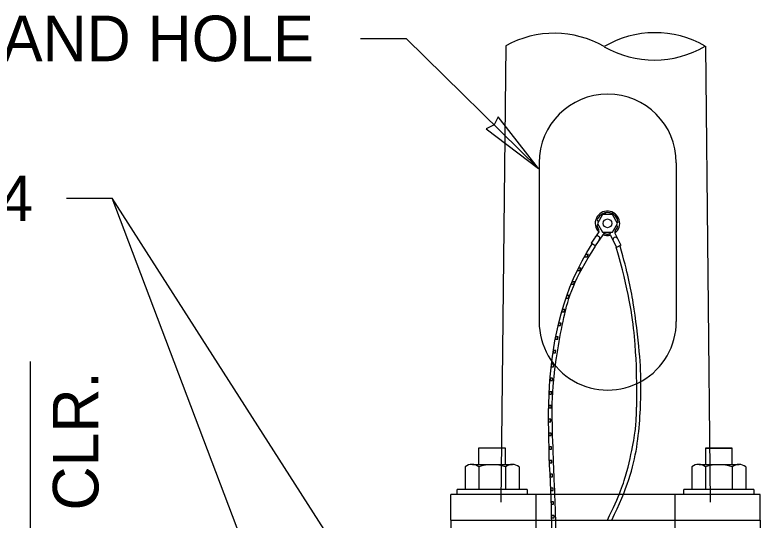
# Model space of a CAD drawing. Extents: x 99862 to 103680, y 99470 to 105076.
# Drawn here: x 101207 to 101468.4, y 103794.6 to 103971.8 of the extents above; entities that cross this region are included whole.
import ezdxf

# ---------------------------------------------------------------- set-up
doc = ezdxf.new("R2010")
doc.units = 0
for name, color, linetype in [('Level 12', 7, 'Continuous'), ('Level 13', 7, 'Continuous'), ('Level 15', 7, 'Continuous'), ('Level 16', 7, 'Continuous'), ('Level 20', 7, 'Continuous'), ('Level 3', 7, 'Continuous'), ('Level 32', 7, 'Continuous'), ('Level 4', 7, 'Continuous'), ('Level 7', 7, 'Continuous'), ('Level 8', 7, 'Continuous')]:
    doc.layers.add(name, color=color, linetype=linetype)

msp = doc.modelspace()

# ---------------------------------------------------------------- linework, layer by layer
at = {"layer": 'Level 12'}
for p, q in [((101390.88, 103919.95), (101390.88, 103864.27)), ((101438.99, 103919.95), (101438.99, 103864.27)), ((101364.96, 103813.37), (101364.96, 103805.45)), ((101367.48, 103814.17), (101381.51, 103814.17)), ((101369.69, 103813.37), (101369.69, 103805.45)), ((101379.14, 103813.29), (101379.14, 103805.37)), ((101383.87, 103813.29), (101383.87, 103805.37)), ((101444.45, 103813.37), (101444.45, 103805.45)), ((101446.97, 103814.17), (101461, 103814.17)), ((101449.18, 103813.37), (101449.18, 103805.45)), ((101458.64, 103813.29), (101458.64, 103805.37)), ((101463.36, 103813.29), (101463.36, 103805.37)), ((101386.72, 103805.41), (101362.11, 103805.41)), ((101362.11, 103803.65), (101362.11, 103805.41)), ((101386.72, 103805.41), (101386.72, 103803.65)), ((101466.21, 103805.41), (101441.6, 103805.41)), ((101441.6, 103803.65), (101441.6, 103805.41)), ((101466.21, 103805.41), (101466.21, 103803.65))]:
    msp.add_line(p, q, dxfattribs=at)
for centre, radius, start, end in [((101414.94, 103919.95), 24.06, 360, 180), ((101414.94, 103864.27), 24.06, 180, 0.0006), ((101367.32, 103810.27), 3.9, 52.6587, 127.3413), ((101374.27, 103798.55), 15.52, 71.7014, 107.1831), ((101381.51, 103810.56), 3.61, 49.0477, 130.9422), ((101446.82, 103810.27), 3.9, 52.6587, 127.3413), ((101453.76, 103798.55), 15.52, 71.7014, 107.1831), ((101461, 103810.56), 3.61, 49.0477, 130.9422)]:
    msp.add_arc(centre, radius, start, end, dxfattribs=at)
at = {"layer": 'Level 13'}
for p, q in [((101359.88, 103794.65), (101359.88, 103803.65)), ((101468.38, 103803.65), (101359.88, 103803.65)), ((101389.71, 103803.65), (101389.71, 103794.65)), ((101438.56, 103794.65), (101438.56, 103803.65)), ((101468.38, 103794.65), (101468.38, 103803.65))]:
    msp.add_line(p, q, dxfattribs=at)
at = {"layer": 'Level 15'}
for p, q in [((101328.28, 103963.52), (101344.28, 103963.52)), ((101390.68, 103917.94), (101344.28, 103963.52)), ((101225.17, 103907.46), (101241.17, 103907.46)), ((101338.32, 103755.87), (101241.17, 103907.46)), ((101312.01, 103720.59), (101241.17, 103907.46)), ((101212.46, 103777.76), (101212.46, 103850.21))]:
    msp.add_line(p, q, dxfattribs=at)
msp.add_lwpolyline([(101390.68, 103917.94), (101376.49, 103936.07), (101375.15, 103933.2), (101372.3, 103931.81)], close=True, dxfattribs=at)
at = {"layer": 'Level 16'}
msp.add_line((101413.66, 103895.64), (101416.05, 103895.64), dxfattribs=at)
msp.add_lwpolyline([(101411.34, 103898.69), (101413.1, 103895.64), (101416.61, 103895.64), (101418.37, 103898.69), (101416.61, 103901.73), (101413.1, 103901.73)], close=True, dxfattribs=at)
at = {"layer": 'Level 3'}
for p, q in [((101359.88, 103794.65), (101359.88, 103769.65)), ((101359.88, 103794.65), (101468.38, 103794.65)), ((101389.71, 103794.65), (101389.71, 103769.65)), ((101438.56, 103769.65), (101438.56, 103794.65)), ((101468.38, 103794.65), (101468.38, 103769.65))]:
    msp.add_line(p, q, dxfattribs=at)
at = {"layer": 'Level 32'}
for p, q in [((101414.15, 103902.38), (101413.7, 103901.73)), ((101416.09, 103902.24), (101416.34, 103901.73)), ((101411.3, 103899.92), (101411.64, 103899.21)), ((101418.55, 103899.39), (101418.23, 103898.92)), ((101411.48, 103898.45), (101411.16, 103897.98)), ((101418.06, 103898.16), (101418.41, 103897.45)), ((101411.77, 103895.68), (101409.11, 103891.75)), ((101413.2, 103894.71), (101410.53, 103890.79)), ((101413.37, 103895.64), (101413.62, 103895.13)), ((101416, 103895.64), (101415.56, 103894.99)), ((101415.92, 103894.51), (101417.98, 103890.24)), ((101417.47, 103895.26), (101419.53, 103890.99)), ((101410.53, 103890.79), (101409.11, 103891.75)), ((101419.53, 103890.99), (101417.98, 103890.24))]:
    msp.add_line(p, q, dxfattribs=at)
for centre, radius, start, end in [((101414.85, 103898.69), 3.76, 70.8363, 160.8363), ((101414.85, 103898.69), 3.76, 10.8363, 100.8363), ((101414.85, 103898.69), 3.76, 190.8363, 214.9248), ((101411.15, 103896.1), 0.75, 325.8363, 34.9248), ((101414.85, 103898.69), 3.76, 316.7413, 340.8363), ((101411.28, 103893.42), 0.861, 325.8363, 145.8363), ((101413.82, 103894.29), 0.75, 76.7413, 145.8363), ((101414.85, 103898.69), 3.76, 250.8363, 270), ((101414.85, 103898.69), 3.76, 270, 280.8363), ((101415.24, 103894.19), 0.75, 25.8363, 94.9248), ((101417.63, 103892.96), 0.861, 25.8363, 205.8363), ((101418.14, 103895.59), 0.75, 136.7413, 205.8363)]:
    msp.add_arc(centre, radius, start, end, dxfattribs=at)
at = {"layer": 'Level 4'}
for p, q in [((101371.04, 103819.86), (101369.67, 103819.86)), ((101371.04, 103819.86), (101369.67, 103819.86)), ((101369.67, 103819.86), (101369.67, 103814.17)), ((101379.05, 103819.86), (101371.04, 103819.86)), ((101379.05, 103819.86), (101371.04, 103819.86)), ((101379.05, 103814.17), (101379.05, 103819.86)), ((101458.6, 103819.86), (101449.22, 103819.86)), ((101449.22, 103819.86), (101449.22, 103814.17)), ((101449.22, 103819.86), (101457.22, 103819.86)), ((101457.22, 103819.86), (101458.6, 103819.86)), ((101458.6, 103814.17), (101458.6, 103819.86))]:
    msp.add_line(p, q, dxfattribs=at)
at = {"layer": 'Level 7'}
msp.add_circle((101414.85, 103898.69), 1.52, dxfattribs=at)
for start, end in [(307.3713, 224.2948), (247.3713, 284.2948)]:
    msp.add_arc((101414.85, 103898.69), 4.3, start, end, dxfattribs=at)
at = {"layer": 'Level 8'}
for p, q in [((101379.21, 103960.96), (101377.4, 103800.9)), ((101449.21, 103960.79), (101450.93, 103800.9)), ((101406.76, 103886.97), (101407.72, 103886.97)), ((101408.2, 103887.8), (101407.23, 103887.8)), ((101404.25, 103882.15), (101405.18, 103882.15)), ((101405.59, 103882.99), (101404.66, 103882.99)), ((101403.37, 103878.17), (101402.46, 103878.17)), ((101402.11, 103877.33), (101403.02, 103877.33)), ((101401.48, 103873.35), (101400.6, 103873.35)), ((101400.3, 103872.51), (101401.19, 103872.51)), ((101398.79, 103867.69), (101399.66, 103867.69)), ((101399.9, 103868.53), (101399.03, 103868.53)), ((101397.54, 103862.87), (101398.4, 103862.87)), ((101398.6, 103863.71), (101397.74, 103863.71)), ((101396.53, 103858.06), (101397.38, 103858.06)), ((101397.54, 103858.89), (101396.69, 103858.89)), ((101395.73, 103853.24), (101396.58, 103853.24)), ((101396.7, 103854.08), (101395.86, 103854.08)), ((101396.06, 103849.26), (101395.22, 103849.26)), ((101395.13, 103848.42), (101395.97, 103848.42)), ((101395.6, 103844.44), (101394.76, 103844.44)), ((101394.69, 103843.6), (101395.53, 103843.6)), ((101394.41, 103838.78), (101395.25, 103838.78)), ((101395.29, 103839.62), (101394.45, 103839.62)), ((101394.25, 103833.96), (101395.09, 103833.96)), ((101395.11, 103834.8), (101394.27, 103834.8)), ((101395.05, 103829.98), (101394.21, 103829.98)), ((101394.21, 103829.15), (101395.05, 103829.15)), ((101395.08, 103825.17), (101394.24, 103825.17)), ((101394.26, 103824.33), (101395.09, 103824.33)), ((101395.19, 103820.35), (101394.35, 103820.35)), ((101394.38, 103819.51), (101395.21, 103819.51)), ((101395.35, 103815.53), (101394.51, 103815.53)), ((101394.55, 103814.69), (101395.38, 103814.69)), ((101395.55, 103810.71), (101394.71, 103810.71)), ((101394.75, 103809.87), (101395.58, 103809.87)), ((101395.76, 103805.89), (101394.92, 103805.89)), ((101394.95, 103805.05), (101395.79, 103805.05)), ((101395.95, 103801.07), (101395.11, 103801.07)), ((101395.14, 103800.24), (101395.98, 103800.24)), ((101396.1, 103796.26), (101395.27, 103796.26)), ((101395.29, 103795.42), (101396.12, 103795.42))]:
    msp.add_line(p, q, dxfattribs=at)
for centre, start, end in [((101396.15, 103930.27), 60, 118.8981), ((101431.55, 103930.47), 60, 120.6407), ((101431.21, 103990.99), 240, 300.6556)]:
    msp.add_arc(centre, 35.06, start, end, dxfattribs=at)
for points, degree in [([(101295.94, 103627.5), (101312.4, 103683.94), (101386.21, 103718.5), (101400.62, 103786.62), (101389.07, 103859.78), (101409.48, 103891.5)], 3), ([(101297.21, 103627.19), (101303.17, 103648), (101312.24, 103663.56), (101332.2, 103688.12), (101343.09, 103697.11), (101358.06, 103709.05), (101362.81, 103712.77), (101369.25, 103718.4), (101371.28, 103720.29), (101375.05, 103724.13), (101376.8, 103726.08), (101384.89, 103735.98), (101389.27, 103744.4), (101394.96, 103762.55), (101396.27, 103772.27), (101396.73, 103785.49), (101396.77, 103788.19), (101396.74, 103793.7), (101396.67, 103796.51), (101396.38, 103805.1), (101396.07, 103811.03), (101395.43, 103829.17), (101395.37, 103841.77), (101399.23, 103866.71), (101403.14, 103879.06), (101410.66, 103890.74)], 3), ([(101414.85, 103794.66), (101419.09, 103803.35), (101421.98, 103811.7), (101424.39, 103823.94), (101424.87, 103827.97), (101425.07, 103832.96), (101425.09, 103833.95), (101425.13, 103835.95), (101425.17, 103838.94), (101424.96, 103857.78), (101422.29, 103875.18), (101417.95, 103890.3)], 3), ([(101416.37, 103794.65), (101421.83, 103805.69), (101426.04, 103820.17), (101426.77, 103842.31), (101426.34, 103852.18), (101423.96, 103871.64), (101422.01, 103881.23), (101419.3, 103890.69)], 3), ([(101407.23, 103887.8), (101407.07, 103887.52), (101406.91, 103887.25), (101406.76, 103886.97)], 2), ([(101407.72, 103886.97), (101407.87, 103887.25), (101408.03, 103887.52), (101408.2, 103887.8)], 2), ([(101404.66, 103882.99), (101404.52, 103882.71), (101404.39, 103882.43), (101404.25, 103882.15)], 2), ([(101405.18, 103882.15), (101405.32, 103882.43), (101405.45, 103882.71), (101405.59, 103882.99)], 2), ([(101402.46, 103878.17), (101402.34, 103877.89), (101402.23, 103877.61), (101402.11, 103877.33)], 2), ([(101403.02, 103877.33), (101403.13, 103877.61), (101403.25, 103877.89), (101403.37, 103878.17)], 2), ([(101400.6, 103873.35), (101400.5, 103873.07), (101400.4, 103872.79), (101400.3, 103872.51)], 2), ([(101401.19, 103872.51), (101401.29, 103872.79), (101401.38, 103873.07), (101401.48, 103873.35)], 2), ([(101399.03, 103868.53), (101398.95, 103868.25), (101398.87, 103867.97), (101398.79, 103867.69)], 2), ([(101399.66, 103867.69), (101399.74, 103867.97), (101399.82, 103868.25), (101399.9, 103868.53)], 2), ([(101397.74, 103863.71), (101397.67, 103863.43), (101397.6, 103863.15), (101397.54, 103862.87)], 2), ([(101398.4, 103862.87), (101398.46, 103863.15), (101398.53, 103863.43), (101398.6, 103863.71)], 2), ([(101396.69, 103858.89), (101396.63, 103858.61), (101396.58, 103858.34), (101396.53, 103858.06)], 2), ([(101397.38, 103858.06), (101397.43, 103858.34), (101397.49, 103858.61), (101397.54, 103858.89)], 2), ([(101395.86, 103854.08), (101395.81, 103853.8), (101395.77, 103853.52), (101395.73, 103853.24)], 2), ([(101396.58, 103853.24), (101396.62, 103853.52), (101396.66, 103853.8), (101396.7, 103854.08)], 2), ([(101395.22, 103849.26), (101395.19, 103848.98), (101395.16, 103848.7), (101395.13, 103848.42)], 2), ([(101395.97, 103848.42), (101396, 103848.7), (101396.03, 103848.98), (101396.06, 103849.26)], 2), ([(101394.76, 103844.44), (101394.74, 103844.16), (101394.71, 103843.88), (101394.69, 103843.6)], 2), ([(101395.53, 103843.6), (101395.55, 103843.88), (101395.57, 103844.16), (101395.6, 103844.44)], 2), ([(101394.45, 103839.62), (101394.43, 103839.34), (101394.42, 103839.06), (101394.41, 103838.78)], 2), ([(101395.25, 103838.78), (101395.26, 103839.06), (101395.27, 103839.34), (101395.29, 103839.62)], 2), ([(101394.27, 103834.8), (101394.27, 103834.52), (101394.26, 103834.24), (101394.25, 103833.96)], 2), ([(101395.09, 103833.96), (101395.1, 103834.24), (101395.1, 103834.52), (101395.11, 103834.8)], 2), ([(101394.21, 103829.98), (101394.21, 103829.7), (101394.21, 103829.43), (101394.21, 103829.15)], 2), ([(101395.05, 103829.15), (101395.05, 103829.43), (101395.05, 103829.7), (101395.05, 103829.98)], 2), ([(101394.24, 103825.17), (101394.25, 103824.89), (101394.25, 103824.61), (101394.26, 103824.33)], 2), ([(101395.09, 103824.33), (101395.09, 103824.61), (101395.08, 103824.89), (101395.08, 103825.17)], 2), ([(101394.35, 103820.35), (101394.36, 103820.07), (101394.37, 103819.79), (101394.38, 103819.51)], 2), ([(101395.21, 103819.51), (101395.2, 103819.79), (101395.2, 103820.07), (101395.19, 103820.35)], 2), ([(101394.51, 103815.53), (101394.52, 103815.25), (101394.54, 103814.97), (101394.55, 103814.69)], 2), ([(101395.38, 103814.69), (101395.37, 103814.97), (101395.36, 103815.25), (101395.35, 103815.53)], 2), ([(101394.71, 103810.71), (101394.72, 103810.43), (101394.73, 103810.15), (101394.75, 103809.87)], 2), ([(101395.58, 103809.87), (101395.57, 103810.15), (101395.56, 103810.43), (101395.55, 103810.71)], 2), ([(101394.92, 103805.89), (101394.93, 103805.61), (101394.94, 103805.33), (101394.95, 103805.05)], 2), ([(101395.79, 103805.05), (101395.78, 103805.33), (101395.77, 103805.61), (101395.76, 103805.89)], 2), ([(101395.11, 103801.07), (101395.12, 103800.79), (101395.13, 103800.51), (101395.14, 103800.24)], 2), ([(101395.98, 103800.24), (101395.97, 103800.51), (101395.96, 103800.79), (101395.95, 103801.07)], 2), ([(101395.27, 103796.26), (101395.27, 103795.98), (101395.28, 103795.7), (101395.29, 103795.42)], 2), ([(101396.12, 103795.42), (101396.12, 103795.7), (101396.11, 103795.98), (101396.1, 103796.26)], 2)]:
    msp.add_open_spline(points, degree=degree, dxfattribs=at)

# ---------------------------------------------------------------- texts
at = {"layer": 'Level 20'}
for s, p in [('HAND HOLE', (101187.04, 103955.52)), ('4  # 4', (101159.88, 103899.46))]:
    msp.add_text(s, height=16, dxfattribs=at).set_placement(p)
msp.add_text('CLR.', height=16, rotation=90, dxfattribs=at).set_placement((101236.34, 103798))

doc.saveas('drawing.dxf')
